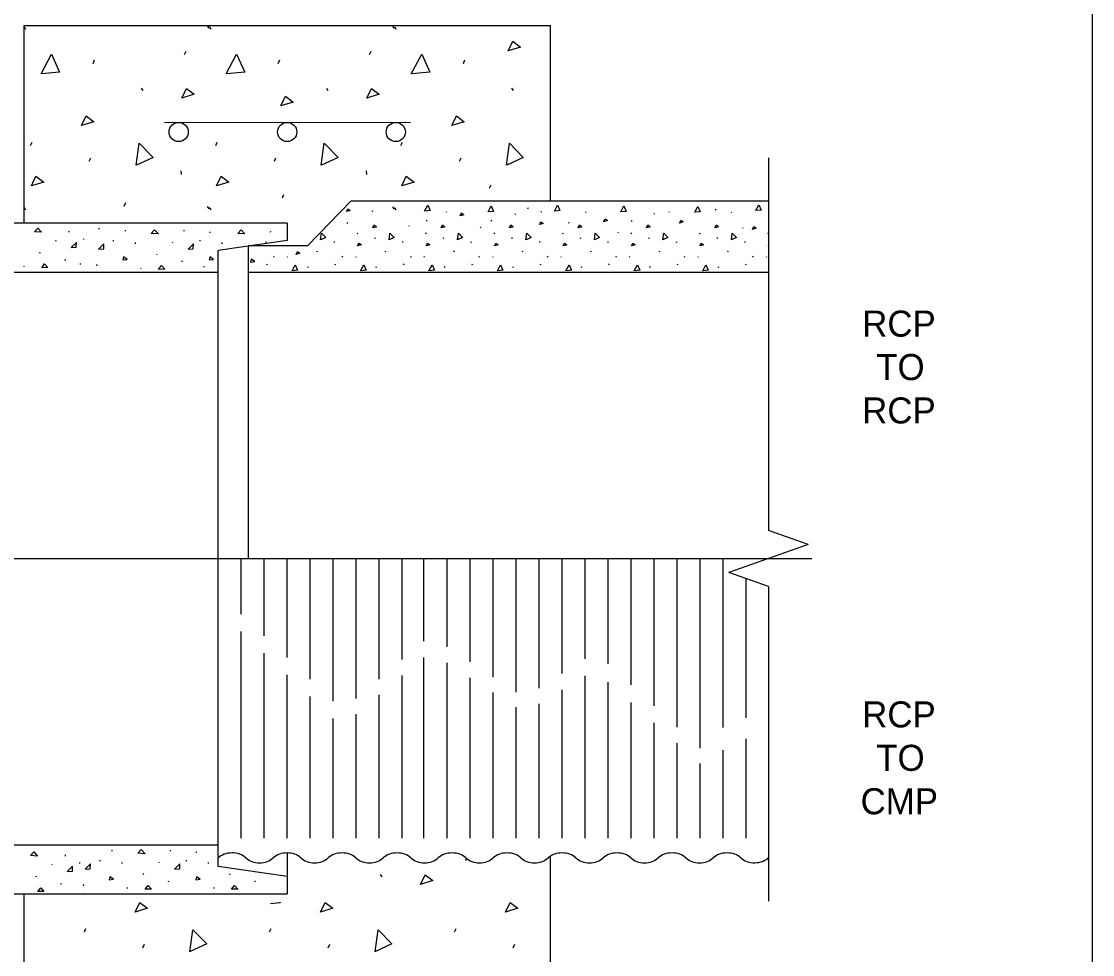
# Model space of a CAD drawing. Extents: x 49991.4 to 50021, y 49987.6 to 50011.4.
# Drawn here: x 50006.148 to 50008.615, y 50008.025 to 50010.174 of the extents above; entities that cross this region are included whole.
import ezdxf

# ---------------------------------------------------------------- set-up
doc = ezdxf.new("R2010")
doc.units = 0
for name, color, linetype in [('Level 1', 7, 'Continuous'), ('Level 2', 7, 'Continuous'), ('Level 5', 7, 'Continuous'), ('Level 6', 7, 'Continuous')]:
    doc.layers.add(name, color=color, linetype=linetype)

msp = doc.modelspace()

# ---------------------------------------------------------------- linework, layer by layer
at = {"layer": 'Level 1'}
for p, q in [((50006.1541, 50009.7099), (50006.1541, 50010.1648)), ((50006.1541, 50010.1648), (50007.3661, 50010.1648)), ((50006.1541, 50010.1618), (50006.1577, 50010.1564)), ((50006.5759, 50010.1638), (50006.5795, 50010.1585)), ((50006.5805, 50010.1618), (50006.584, 50010.1564)), ((50007.0023, 50010.1638), (50007.0059, 50010.1585)), ((50007.0069, 50010.1618), (50007.0104, 50010.1564)), ((50007.3661, 50009.7599), (50007.3661, 50010.1648)), ((50006.5235, 50010.098), (50006.5271, 50010.106)), ((50006.9499, 50010.098), (50006.9535, 50010.106)), ((50006.3131, 50010.0775), (50006.3166, 50010.0855)), ((50006.7394, 50010.0775), (50006.743, 50010.0855)), ((50007.1658, 50010.0775), (50007.1694, 50010.0855)), ((50006.4241, 50010.0207), (50006.4276, 50010.0154)), ((50006.8504, 50010.0207), (50006.854, 50010.0154)), ((50007.2768, 50010.0207), (50007.2804, 50010.0154)), ((50006.4775, 50009.9416), (50007.0439, 50009.9421)), ((50006.1692, 50009.8884), (50006.1728, 50009.8964)), ((50006.5956, 50009.8884), (50006.5991, 50009.8964)), ((50007.022, 50009.8884), (50007.0255, 50009.8964)), ((50006.3042, 50009.852), (50006.3077, 50009.86)), ((50006.7306, 50009.852), (50006.7341, 50009.86)), ((50007.1569, 50009.852), (50007.1605, 50009.86)), ((50006.5153, 50009.8297), (50006.5162, 50009.8217)), ((50006.9417, 50009.8297), (50006.9426, 50009.8217)), ((50007.226, 50009.7898), (50007.2296, 50009.7978)), ((50006.7489, 50009.7675), (50006.7524, 50009.7755)), ((50006.1541, 50009.746), (50006.1577, 50009.7406)), ((50006.385, 50009.749), (50006.3885, 50009.757)), ((50006.5759, 50009.748), (50006.5795, 50009.7427)), ((50006.5805, 50009.746), (50006.584, 50009.7406)), ((50006.9065, 50009.7599), (50006.8067, 50009.657)), ((50007.8685, 50009.7599), (50006.9065, 50009.7599)), ((50006.9562, 50009.7364), (50006.9573, 50009.7388)), ((50007.0023, 50009.748), (50007.0059, 50009.7427)), ((50007.0069, 50009.746), (50007.0104, 50009.7406)), ((50007.1261, 50009.7364), (50007.1272, 50009.7348)), ((50007.3143, 50009.7429), (50007.3154, 50009.7453)), ((50007.3445, 50009.7364), (50007.3456, 50009.7348)), ((50007.6388, 50009.7364), (50007.6399, 50009.7348)), ((50007.7465, 50009.7392), (50007.7476, 50009.7416)), ((50006.8984, 50009.7091), (50006.8994, 50009.7115)), ((50007.0811, 50009.7143), (50007.0822, 50009.7167)), ((50007.2301, 50009.7143), (50007.2312, 50009.7167)), ((50007.2844, 50009.7309), (50007.2855, 50009.7293)), ((50007.4075, 50009.7115), (50007.4086, 50009.7099)), ((50007.4473, 50009.7355), (50007.4484, 50009.7339)), ((50007.5531, 50009.7134), (50007.5542, 50009.7158)), ((50007.6046, 50009.7318), (50007.6057, 50009.7302)), ((50007.7823, 50009.7355), (50007.7834, 50009.7339)), ((50006.7601, 50009.7099), (50005.3784, 50009.7099)), ((50006.2584, 50009.6886), (50006.2584, 50009.6912)), ((50006.3275, 50009.6954), (50006.3275, 50009.6978)), ((50006.3877, 50009.6909), (50006.3877, 50009.6935)), ((50006.5226, 50009.6909), (50006.5226, 50009.6935)), ((50006.5826, 50009.6872), (50006.5826, 50009.6896)), ((50006.7217, 50009.6887), (50006.7227, 50009.6911)), ((50006.7601, 50009.7099), (50006.7601, 50009.6699)), ((50006.9218, 50009.685), (50006.9229, 50009.6874)), ((50007.04, 50009.7042), (50007.0411, 50009.7026)), ((50007.0794, 50009.685), (50007.0805, 50009.6874)), ((50007.2048, 50009.7005), (50007.2059, 50009.6989)), ((50007.237, 50009.685), (50007.2381, 50009.6874)), ((50007.3946, 50009.685), (50007.3957, 50009.6874)), ((50007.5213, 50009.6885), (50007.5224, 50009.6869)), ((50007.5522, 50009.685), (50007.5533, 50009.6874)), ((50007.7099, 50009.685), (50007.7109, 50009.6874)), ((50007.8082, 50009.6996), (50007.8093, 50009.698)), ((50007.8675, 50009.685), (50007.8685, 50009.6874)), ((50006.2279, 50009.6677), (50006.2271, 50009.6695)), ((50006.2919, 50009.6716), (50006.2919, 50009.6738)), ((50006.3604, 50009.668), (50006.3604, 50009.6702)), ((50006.411, 50009.6623), (50006.411, 50009.6649)), ((50006.4971, 50009.6641), (50006.4963, 50009.6659)), ((50006.5596, 50009.668), (50006.5596, 50009.6702)), ((50006.7601, 50009.6699), (50006.6011, 50009.6469)), ((50006.6102, 50009.6623), (50006.6102, 50009.6649)), ((50006.7104, 50009.6674), (50006.7107, 50009.665)), ((50006.868, 50009.6674), (50006.8683, 50009.665)), ((50006.9623, 50009.6741), (50006.9634, 50009.6765)), ((50007.0256, 50009.6674), (50007.0259, 50009.665)), ((50007.1199, 50009.6741), (50007.121, 50009.6765)), ((50007.1832, 50009.6674), (50007.1835, 50009.665)), ((50007.2775, 50009.6741), (50007.2786, 50009.6765)), ((50007.3409, 50009.6674), (50007.3411, 50009.665)), ((50007.4351, 50009.6741), (50007.4362, 50009.6765)), ((50007.4985, 50009.6674), (50007.4987, 50009.665)), ((50007.5927, 50009.6741), (50007.5938, 50009.6765)), ((50007.6561, 50009.6674), (50007.6563, 50009.665)), ((50007.7503, 50009.6741), (50007.7514, 50009.6765)), ((50007.8137, 50009.6674), (50007.814, 50009.665)), ((50006.1908, 50009.6407), (50006.1916, 50009.6428)), ((50006.4598, 50009.6371), (50006.4608, 50009.6392)), ((50006.6011, 50008.2278), (50006.6011, 50009.6469)), ((50006.6709, 50008.9373), (50006.6709, 50009.657)), ((50006.8067, 50009.657), (50006.6709, 50009.657)), ((50006.8289, 50009.6432), (50006.83, 50009.6456)), ((50006.9865, 50009.6432), (50006.9876, 50009.6456)), ((50007.1441, 50009.6432), (50007.1452, 50009.6456)), ((50007.3018, 50009.6432), (50007.3028, 50009.6456)), ((50007.4594, 50009.6432), (50007.4604, 50009.6456)), ((50007.617, 50009.6432), (50007.618, 50009.6456)), ((50007.7746, 50009.6432), (50007.7757, 50009.6456)), ((50006.249, 50009.6238), (50006.2493, 50009.6264)), ((50006.2838, 50009.6146), (50006.2838, 50009.617)), ((50006.3219, 50009.6114), (50006.3225, 50009.614)), ((50006.518, 50009.6202), (50006.5185, 50009.6228)), ((50006.7129, 50009.6135), (50006.7139, 50009.6158)), ((50006.7286, 50009.6332), (50006.7297, 50009.6316)), ((50006.7597, 50009.6326), (50006.7607, 50009.631)), ((50006.8705, 50009.6135), (50006.8715, 50009.6158)), ((50006.8862, 50009.6332), (50006.8873, 50009.6316)), ((50006.9173, 50009.6326), (50006.9183, 50009.631)), ((50007.0281, 50009.6135), (50007.0292, 50009.6158)), ((50007.0438, 50009.6332), (50007.0449, 50009.6316)), ((50007.0749, 50009.6326), (50007.0759, 50009.631)), ((50007.1857, 50009.6135), (50007.1868, 50009.6158)), ((50007.2014, 50009.6332), (50007.2025, 50009.6316)), ((50007.2325, 50009.6326), (50007.2336, 50009.631)), ((50007.3433, 50009.6135), (50007.3444, 50009.6158)), ((50007.359, 50009.6332), (50007.3601, 50009.6316)), ((50007.3901, 50009.6326), (50007.3912, 50009.631)), ((50007.5009, 50009.6135), (50007.502, 50009.6158)), ((50007.5166, 50009.6332), (50007.5177, 50009.6316)), ((50007.5477, 50009.6326), (50007.5488, 50009.631)), ((50007.6585, 50009.6135), (50007.6596, 50009.6158)), ((50007.6743, 50009.6332), (50007.6753, 50009.6316)), ((50007.7053, 50009.6326), (50007.7064, 50009.631)), ((50007.8162, 50009.6135), (50007.8172, 50009.6158)), ((50007.8319, 50009.6332), (50007.8329, 50009.6316)), ((50007.8629, 50009.6326), (50007.864, 50009.631)), ((50005.3784, 50009.5969), (50006.6011, 50009.5969)), ((50006.1544, 50009.6086), (50006.1544, 50009.6106)), ((50006.3021, 50009.6035), (50006.3021, 50009.6035)), ((50006.3219, 50009.5999), (50006.3219, 50009.5999)), ((50006.4234, 50009.605), (50006.4236, 50009.607)), ((50006.5686, 50009.6083), (50006.5697, 50009.6107)), ((50006.6709, 50009.5969), (50007.8685, 50009.5969)), ((50006.8073, 50009.6073), (50006.8084, 50009.6097)), ((50006.965, 50009.6073), (50006.966, 50009.6097)), ((50007.1226, 50009.6073), (50007.1236, 50009.6097)), ((50007.2802, 50009.6073), (50007.2812, 50009.6097)), ((50007.4378, 50009.6073), (50007.4389, 50009.6097)), ((50007.5954, 50009.6073), (50007.5965, 50009.6097)), ((50007.753, 50009.6073), (50007.7541, 50009.6097)), ((50006.6541, 50008.8092), (50006.6541, 50008.9373)), ((50006.7071, 50008.7592), (50006.7071, 50008.9373)), ((50006.7601, 50008.7091), (50006.7601, 50008.9373)), ((50006.8131, 50008.6591), (50006.8131, 50008.9373)), ((50006.8661, 50008.6088), (50006.8661, 50008.9373)), ((50006.9191, 50008.6147), (50006.9191, 50008.9373)), ((50006.9721, 50008.6597), (50006.9721, 50008.9373)), ((50007.0251, 50008.7047), (50007.0251, 50008.9373)), ((50007.0751, 50008.7472), (50007.0751, 50008.9373)), ((50007.1281, 50008.7338), (50007.1281, 50008.9373)), ((50007.1811, 50008.699), (50007.1811, 50008.9373)), ((50007.2341, 50008.6643), (50007.2341, 50008.9373)), ((50007.2871, 50008.6295), (50007.2871, 50008.9373)), ((50007.3401, 50008.639), (50007.3401, 50008.9373)), ((50007.3931, 50008.6725), (50007.3931, 50008.9373)), ((50007.4461, 50008.706), (50007.4461, 50008.9373)), ((50007.4991, 50008.6949), (50007.4991, 50008.9373)), ((50007.5521, 50008.6463), (50007.5521, 50008.9373)), ((50007.6051, 50008.5977), (50007.6051, 50008.9373)), ((50007.6581, 50008.5491), (50007.6581, 50008.9373)), ((50007.7111, 50008.5005), (50007.7111, 50008.9373)), ((50007.7641, 50008.5482), (50007.7641, 50008.9373)), ((50007.8171, 50008.57), (50007.8171, 50008.8907)), ((50006.6541, 50008.2928), (50006.6541, 50008.7692)), ((50006.7071, 50008.2928), (50006.7071, 50008.7192)), ((50007.0751, 50008.2928), (50007.0751, 50008.7095)), ((50007.1281, 50008.2928), (50007.1281, 50008.6966)), ((50006.7601, 50008.2928), (50006.7601, 50008.6691)), ((50007.0251, 50008.2928), (50007.0251, 50008.6676)), ((50007.1811, 50008.2928), (50007.1811, 50008.6627)), ((50007.4461, 50008.2928), (50007.4461, 50008.6674)), ((50007.4991, 50008.2928), (50007.4991, 50008.6526)), ((50007.2341, 50008.2928), (50007.2341, 50008.6288)), ((50007.3931, 50008.2928), (50007.3931, 50008.6349)), ((50006.8131, 50008.2928), (50006.8131, 50008.6191)), ((50006.9721, 50008.2928), (50006.9721, 50008.6233)), ((50007.3401, 50008.2928), (50007.3401, 50008.6023)), ((50007.5521, 50008.2928), (50007.5521, 50008.6056)), ((50006.9191, 50008.2928), (50006.9191, 50008.5789)), ((50007.2871, 50008.2928), (50007.2871, 50008.595)), ((50006.8661, 50008.2928), (50006.8661, 50008.5691)), ((50007.6051, 50008.2928), (50007.6051, 50008.5587)), ((50007.6581, 50008.2928), (50007.6581, 50008.5118)), ((50007.8171, 50008.2928), (50007.8171, 50008.5218)), ((50007.7641, 50008.2928), (50007.7641, 50008.4962)), ((50007.7111, 50008.2928), (50007.7111, 50008.4649)), ((50005.3784, 50008.2778), (50006.6011, 50008.2778)), ((50006.3567, 50008.2632), (50006.3567, 50008.2658)), ((50006.4916, 50008.2632), (50006.4916, 50008.2658)), ((50006.5516, 50008.2595), (50006.5516, 50008.2619)), ((50006.7601, 50008.2592), (50006.7601, 50008.1648)), ((50006.2188, 50008.231), (50006.218, 50008.2328)), ((50006.2493, 50008.2519), (50006.2493, 50008.2545)), ((50006.2828, 50008.2349), (50006.2828, 50008.2371)), ((50006.3294, 50008.2403), (50006.3294, 50008.2425)), ((50006.38, 50008.2346), (50006.38, 50008.2372)), ((50006.4661, 50008.2364), (50006.4653, 50008.2382)), ((50006.5286, 50008.2403), (50006.5286, 50008.2425)), ((50006.5792, 50008.2346), (50006.5792, 50008.2372)), ((50007.3661, 50007.6648), (50007.3661, 50008.2517)), ((50006.4288, 50008.2094), (50006.4298, 50008.2115)), ((50006.7601, 50008.2048), (50006.6011, 50008.2278)), ((50006.6281, 50008.2094), (50006.6289, 50008.2115)), ((50006.9742, 50008.2095), (50006.9777, 50008.2042)), ((50006.1817, 50008.204), (50006.1825, 50008.2061)), ((50006.2399, 50008.1871), (50006.2402, 50008.1897)), ((50006.2909, 50008.1837), (50006.2915, 50008.1863)), ((50006.487, 50008.1925), (50006.4875, 50008.1951)), ((50006.6863, 50008.1925), (50006.6866, 50008.1951)), ((50005.3784, 50008.1648), (50006.7601, 50008.1648)), ((50006.1541, 50007.6648), (50006.1541, 50008.1648)), ((50006.2909, 50008.1722), (50006.2909, 50008.1722)), ((50006.293, 50008.1668), (50006.293, 50008.1668)), ((50006.3924, 50008.1773), (50006.3926, 50008.1793)), ((50006.5917, 50008.1773), (50006.5917, 50008.1793)), ((50006.293, 50008.0772), (50006.2965, 50008.0852)), ((50006.7193, 50008.0772), (50006.7229, 50008.0852)), ((50007.1457, 50008.0772), (50007.1493, 50008.0852)), ((50006.4279, 50008.0408), (50006.4315, 50008.0488)), ((50006.8543, 50008.0408), (50006.8579, 50008.0488)), ((50007.2807, 50008.0408), (50007.2842, 50008.0488))]:
    msp.add_line(p, q, dxfattribs=at)
for points in [[(50008.6146, 50011.2628), (50000.3356, 50011.2628), (50000.3356, 50000.0624), (50008.6146, 50000.0624)], [(50006.1779, 50009.6896), (50006.186, 50009.698), (50006.1946, 50009.6885)], [(50006.4471, 50009.686), (50006.4549, 50009.6944), (50006.4638, 50009.6849)], [(50006.6462, 50009.686), (50006.6543, 50009.6944), (50006.6629, 50009.6849)], [(50006.2745, 50009.6539), (50006.275, 50009.6653), (50006.2627, 50009.6532)], [(50006.3375, 50009.6503), (50006.3381, 50009.6617), (50006.3258, 50009.6496)], [(50006.5435, 50009.6503), (50006.5442, 50009.6617), (50006.5319, 50009.6496)], [(50006.1948, 50009.6068), (50006.2016, 50009.6158), (50006.2092, 50009.6072)], [(50006.3813, 50009.6248), (50006.3914, 50009.6261), (50006.3828, 50009.6319)], [(50006.5804, 50009.6248), (50006.5904, 50009.6261), (50006.5819, 50009.6319)], [(50006.6758, 50009.6196), (50006.6858, 50009.6209), (50006.6773, 50009.6267)], [(50006.4641, 50009.6032), (50006.4706, 50009.6122), (50006.4785, 50009.6036)], [(50006.1688, 50008.2529), (50006.1769, 50008.2613), (50006.1855, 50008.2518)], [(50006.4161, 50008.2583), (50006.4239, 50008.2667), (50006.4328, 50008.2572)], [(50006.3065, 50008.2226), (50006.3071, 50008.234), (50006.2948, 50008.2219)], [(50006.5125, 50008.2226), (50006.5132, 50008.234), (50006.5009, 50008.2219)], [(50006.2654, 50008.2172), (50006.2659, 50008.2286), (50006.2536, 50008.2165)], [(50006.3503, 50008.1971), (50006.3604, 50008.1984), (50006.3518, 50008.2042)], [(50006.4331, 50008.1755), (50006.4396, 50008.1845), (50006.4475, 50008.1759)], [(50006.5494, 50008.1971), (50006.5594, 50008.1984), (50006.5509, 50008.2042)], [(50006.6321, 50008.1755), (50006.6389, 50008.1845), (50006.6465, 50008.1759)], [(50006.1857, 50008.1701), (50006.1925, 50008.1791), (50006.2001, 50008.1705)]]:
    msp.add_lwpolyline(points, close=True, dxfattribs=at)
for points in [[(50007.2691, 50010.1064), (50007.2797, 50010.1286), (50007.2975, 50010.1152), (50007.2691, 50010.1064)], [(50006.1932, 50010.0536), (50006.2172, 50010.0989), (50006.2358, 50010.0571), (50006.1941, 50010.0536)], [(50006.6196, 50010.0536), (50006.6435, 50010.0989), (50006.6622, 50010.0571), (50006.6204, 50010.0536)], [(50007.0459, 50010.0536), (50007.0699, 50010.0989), (50007.0886, 50010.0571), (50007.0468, 50010.0536)], [(50006.5173, 50009.9976), (50006.528, 50010.0198), (50006.5457, 50010.0065), (50006.5173, 50009.9976)], [(50006.9437, 50009.9976), (50006.9543, 50010.0198), (50006.9721, 50010.0065), (50006.9437, 50009.9976)], [(50006.7458, 50009.9794), (50006.7564, 50010.0017), (50006.7742, 50009.9883), (50006.7458, 50009.9794)], [(50006.2866, 50009.9341), (50006.2973, 50009.9564), (50006.315, 50009.943), (50006.2866, 50009.9341)], [(50007.1393, 50009.9341), (50007.15, 50009.9564), (50007.1678, 50009.943), (50007.1393, 50009.9341)], [(50006.4122, 50009.8428), (50006.4193, 50009.8936), (50006.4511, 50009.8607), (50006.4131, 50009.8431)], [(50006.8386, 50009.8428), (50006.8456, 50009.8936), (50006.8774, 50009.8607), (50006.8394, 50009.8431)], [(50007.265, 50009.8428), (50007.272, 50009.8936), (50007.3038, 50009.8607), (50007.2658, 50009.8431)], [(50006.171, 50009.7952), (50006.1816, 50009.8174), (50006.1994, 50009.804), (50006.171, 50009.7952)], [(50006.5974, 50009.7952), (50006.608, 50009.8174), (50006.6258, 50009.804), (50006.5974, 50009.7952)], [(50007.0237, 50009.7952), (50007.0344, 50009.8174), (50007.0521, 50009.804), (50007.0237, 50009.7952)], [(50006.8965, 50009.7362), (50006.8997, 50009.7429), (50006.905, 50009.7389), (50006.8965, 50009.7362)], [(50007.0764, 50009.7374), (50007.0836, 50009.751), (50007.0892, 50009.7385), (50007.0767, 50009.7374)], [(50007.2227, 50009.7356), (50007.2299, 50009.7492), (50007.2355, 50009.7367), (50007.223, 50009.7356)], [(50007.3754, 50009.7374), (50007.3826, 50009.751), (50007.3882, 50009.7385), (50007.3757, 50009.7374)], [(50007.5281, 50009.7356), (50007.5353, 50009.7492), (50007.5409, 50009.7367), (50007.5284, 50009.7356)], [(50007.6984, 50009.7347), (50007.7056, 50009.7483), (50007.7112, 50009.7358), (50007.6987, 50009.7347)], [(50007.839, 50009.7384), (50007.8462, 50009.752), (50007.8518, 50009.7395), (50007.8393, 50009.7384)], [(50007.1584, 50009.7264), (50007.1616, 50009.7331), (50007.1669, 50009.7291), (50007.1584, 50009.7264)], [(50007.3407, 50009.7061), (50007.3439, 50009.7128), (50007.3492, 50009.7088), (50007.3407, 50009.7061)], [(50007.4888, 50009.7126), (50007.492, 50009.7193), (50007.4973, 50009.7153), (50007.4888, 50009.7126)], [(50007.6637, 50009.7098), (50007.6669, 50009.7165), (50007.6722, 50009.7125), (50007.6637, 50009.7098)], [(50006.8371, 50009.6713), (50006.8392, 50009.6866), (50006.8487, 50009.6767), (50006.8373, 50009.6714)], [(50006.957, 50009.6987), (50006.9602, 50009.7054), (50006.9655, 50009.7014), (50006.957, 50009.6987)], [(50006.9947, 50009.6713), (50006.9968, 50009.6866), (50007.0063, 50009.6767), (50006.9949, 50009.6714)], [(50007.1146, 50009.6987), (50007.1178, 50009.7054), (50007.1231, 50009.7014), (50007.1146, 50009.6987)], [(50007.1523, 50009.6713), (50007.1544, 50009.6866), (50007.164, 50009.6767), (50007.1526, 50009.6714)], [(50007.2722, 50009.6987), (50007.2754, 50009.7054), (50007.2808, 50009.7014), (50007.2722, 50009.6987)], [(50007.3099, 50009.6713), (50007.312, 50009.6866), (50007.3216, 50009.6767), (50007.3102, 50009.6714)], [(50007.4298, 50009.6987), (50007.433, 50009.7054), (50007.4384, 50009.7014), (50007.4298, 50009.6987)], [(50007.4675, 50009.6713), (50007.4696, 50009.6866), (50007.4792, 50009.6767), (50007.4678, 50009.6714)], [(50007.5875, 50009.6987), (50007.5907, 50009.7054), (50007.596, 50009.7014), (50007.5875, 50009.6987)], [(50007.6251, 50009.6713), (50007.6273, 50009.6866), (50007.6368, 50009.6767), (50007.6254, 50009.6714)], [(50007.7451, 50009.6987), (50007.7483, 50009.7054), (50007.7536, 50009.7014), (50007.7451, 50009.6987)], [(50007.7828, 50009.6713), (50007.7849, 50009.6866), (50007.7944, 50009.6767), (50007.783, 50009.6714)], [(50007.8312, 50009.6951), (50007.8344, 50009.7018), (50007.8397, 50009.6978), (50007.8312, 50009.6951)], [(50006.9223, 50009.6571), (50006.9255, 50009.6637), (50006.9309, 50009.6597), (50006.9223, 50009.6571)], [(50007.0799, 50009.6571), (50007.0831, 50009.6637), (50007.0885, 50009.6597), (50007.0799, 50009.6571)], [(50007.2376, 50009.6571), (50007.2407, 50009.6637), (50007.2461, 50009.6597), (50007.2376, 50009.6571)], [(50007.3952, 50009.6571), (50007.3984, 50009.6637), (50007.4037, 50009.6597), (50007.3952, 50009.6571)], [(50007.5528, 50009.6571), (50007.556, 50009.6637), (50007.5613, 50009.6597), (50007.5528, 50009.6571)], [(50007.7104, 50009.6571), (50007.7136, 50009.6637), (50007.7189, 50009.6597), (50007.7104, 50009.6571)], [(50006.7808, 50009.6377), (50006.784, 50009.6443), (50006.7893, 50009.6403), (50006.7808, 50009.6377)], [(50007.868, 50009.6571), (50007.8685, 50009.6581)], [(50007.8685, 50009.6573), (50007.868, 50009.6571)], [(50006.7714, 50009.6001), (50006.7786, 50009.6137), (50006.7842, 50009.6012), (50006.7716, 50009.6001)], [(50006.929, 50009.6001), (50006.9362, 50009.6137), (50006.9418, 50009.6012), (50006.9293, 50009.6001)], [(50007.0866, 50009.6001), (50007.0938, 50009.6137), (50007.0994, 50009.6012), (50007.0869, 50009.6001)], [(50007.2442, 50009.6001), (50007.2514, 50009.6137), (50007.257, 50009.6012), (50007.2445, 50009.6001)], [(50007.4018, 50009.6001), (50007.409, 50009.6137), (50007.4146, 50009.6012), (50007.4021, 50009.6001)], [(50007.5594, 50009.6001), (50007.5666, 50009.6137), (50007.5722, 50009.6012), (50007.5597, 50009.6001)], [(50007.717, 50009.6001), (50007.7242, 50009.6137), (50007.7298, 50009.6012), (50007.7173, 50009.6001)], [(50007.1697, 50008.2424), (50007.1703, 50008.2436)], [(50007.1733, 50008.2426), (50007.1706, 50008.2424)], [(50007.0674, 50008.1864), (50007.0781, 50008.2086), (50007.0958, 50008.1953), (50007.0674, 50008.1864)], [(50006.4103, 50008.123), (50006.421, 50008.1452), (50006.4388, 50008.1318), (50006.4103, 50008.123)], [(50006.743, 50008.1465), (50006.744, 50008.1442), (50006.7219, 50008.1423)], [(50006.8367, 50008.123), (50006.8474, 50008.1452), (50006.8651, 50008.1318), (50006.8367, 50008.123)], [(50007.2631, 50008.123), (50007.2738, 50008.1452), (50007.2915, 50008.1318), (50007.2631, 50008.123)], [(50006.536, 50008.0316), (50006.543, 50008.0824), (50006.5748, 50008.0495), (50006.5368, 50008.0319)], [(50006.9623, 50008.0316), (50006.9694, 50008.0824), (50007.0012, 50008.0495), (50006.9632, 50008.0319)]]:
    msp.add_lwpolyline(points, dxfattribs=at)
for centre in [(50006.5101, 50009.9195), (50006.7601, 50009.9195), (50007.0101, 50009.9195)]:
    msp.add_circle(centre, 0.0221, dxfattribs=at)
for centre, start_param, end_param in [((50006.6331, 50008.2308), 3.785478, 5.655429), ((50006.7598, 50008.2308), 3.785478, 5.6393), ((50006.8864, 50008.2308), 3.785478, 5.6393), ((50007.013, 50008.2308), 3.785478, 5.6393), ((50007.1397, 50008.2308), 3.785478, 5.6393), ((50007.2663, 50008.2308), 3.785478, 5.6393), ((50007.3929, 50008.2308), 3.785478, 5.6393), ((50007.5196, 50008.2308), 3.785478, 5.6393), ((50007.6462, 50008.2308), 3.785478, 5.6393), ((50007.7729, 50008.2308), 3.785478, 5.6393), ((50006.6964, 50008.2649), 0.643885, 2.497707), ((50006.8231, 50008.2649), 0.643885, 2.497707), ((50006.9497, 50008.2649), 0.643885, 2.497707), ((50007.0764, 50008.2649), 0.642693, 2.497707), ((50007.203, 50008.2649), 0.643885, 2.497707), ((50007.3296, 50008.2649), 0.643885, 2.497707), ((50007.4563, 50008.2649), 0.643885, 2.497707), ((50007.5829, 50008.2649), 0.643885, 2.497707), ((50007.7095, 50008.2649), 0.643885, 2.497707), ((50007.8363, 50008.2649), 0.643885, 2.522888)]:
    msp.add_ellipse(centre, major_axis=(-0.0396, 0), ratio=0.716482, start_param=start_param, end_param=end_param, dxfattribs=at)
at = {"layer": 'Level 5'}
msp.add_line((50005.2784, 50008.9373), (50007.9685, 50008.9373), dxfattribs=at)
at = {"layer": 'Level 6'}
for p, q in [((50007.8685, 50009.8599), (50007.8685, 50009.0021)), ((50007.9599, 50008.9697), (50007.8685, 50009.0021)), ((50007.9599, 50008.9697), (50007.8685, 50008.9373)), ((50007.8685, 50008.9373), (50007.7771, 50008.9049)), ((50007.8685, 50008.8725), (50007.7771, 50008.9049)), ((50007.8685, 50008.8725), (50007.8685, 50008.1484))]:
    msp.add_line(p, q, dxfattribs=at)

# ---------------------------------------------------------------- texts
at = {"layer": 'Level 2'}
for s, p in [('RCP', (50008.0841, 50009.4482)), ('TO', (50008.1165, 50009.3482)), ('RCP', (50008.0841, 50009.2482)), ('RCP', (50008.0841, 50008.5482)), ('TO', (50008.1165, 50008.4482)), ('CMP', (50008.0804, 50008.3482))]:
    msp.add_text(s, height=0.06, dxfattribs=at).set_placement(p)

doc.saveas('drawing.dxf')
